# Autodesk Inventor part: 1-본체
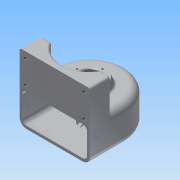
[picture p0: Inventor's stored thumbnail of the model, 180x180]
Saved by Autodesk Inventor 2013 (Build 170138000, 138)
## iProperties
Created: 2015-02
Part Number: 1-본체
Material: 알루미늄 6061
Document SubType Name: Modeling
Designer: Administrator
Density: 2.40731 g/cm^3
Mass: 511.135 g
Surface Area: 707.804 cm^2
Volume: 212.326 cm^3
Author: Administrator
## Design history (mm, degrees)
sketch "스케치1"
  geometry: L1 (-50, 0)-(-50, -50); L2 (50, 0)-(50, -50); L3 (-50, -50)-(50, -50); A1 r 50 centre (0, 0) between (-50, 0) and (50, 0); 1 further point
  constraints: 6 end point, 2 point on circle, 2 tangent, 1 centre point, 1 coincident, 1 parallel, 1 perpendicular, 1 vertical
  dimensions: "d0" = 100 diameter of A1; "d2" = 50 distance from line of L3 point (0, 0)
extrude "돌출1" new body sketch "스케치1" distance "d3" = 50; taper "d4" = 0 deg
feature "쉘1" dims "d5" = 4
sketch "스케치2"
  geometry: L1 (-50, 0)-(-50, -50) reference; L2 (-50, -50)-(50, -50) reference; L3 (50, -50)-(50, 0) reference; L4 (-50, -20)-(-34.641, -20); L5 (50, -20)-(34.641, -20); A1 r 50 centre (0, 0) between (50, 0) and (-50, 0) reference; A2 r 40 centre (0, 0) between (-34.641, -20) and (34.641, -20)
  constraints: 4 end point, 2 collinear, 2 point on circle, 2 point on line, 1 centre point, 1 coincident, 1 perpendicular
  dimensions: "d6" = 80 diameter of A2; "d9" = 30 distance between parallel lines of L2 L4
extrude "돌출2" join sketch "스케치2" distance "d10" = 45; taper "d11" = 0 deg
sketch "스케치3"
  geometry: C1 r 25 at (0, 0); A1 r 40 centre (0, 0) between (-34.641, -20) and (34.641, -20) reference
  constraints: 1 centre point, 1 coincident
  dimensions: "d12" = 50 diameter of C1
extrude "돌출3" join sketch "스케치3" distance "d14" = 10; taper "d15" = -20 deg
sketch "스케치4"
  geometry: C1 r 20 at (0, 0); A1 r 50 centre (0, 0) between (50, 0) and (-50, 0) reference
  constraints: 1 centre point, 1 coincident
  dimensions: "d16" = 40 diameter of C1
extrude "돌출4" join sketch "스케치4" distance "d18" = 9; taper "d19" = 0 deg
hole "구멍1" diameter "d22" = 20; stored, may be unused: countersink angle "d26" = 90 deg, drill point angle "d28" = 118 deg; dims "d23" = 6, "d24" = 28, "d25" = 10, "d27" = 8, "d29" = 10, "d30" = 10
hole "구멍2" diameter "d33" = 20; stored, may be unused: countersink angle "d37" = 90 deg, drill point angle "d39" = 0 deg; dims "d34" = 6, "d35" = 28, "d36" = 8, "d38" = 10, "d40" = 10, "d41" = 10
sketch "스케치5"
  geometry: L1 (0, 95)-(100, 95) reference; L2 (8.25, 86)-(91.75, 86); L3 (91.75, 86)-(91.75, 53); L4 (91.75, 53)-(8.25, 53); L5 (8.25, 53)-(8.25, 86); L6 (0, 50)-(0, 95) reference; 7 further points
  constraints: 8 end point, 4 coincident, 2 midpoint, 2 parallel, 1 horizontal, 1 perpendicular, 1 vertical alignment
  dimensions: "d42" = 83.5 distance of L2.start L2.end; "d44" = 33 distance of L4.end L2.start; "d72" = 9 distance between parallel lines of L2 L1
hole "구멍3" sketch "스케치5" at (8.25, 86), (8.25, 53), (91.75, 53), (91.75, 86) diameter "d45" = 5.134; stored, may be unused: countersink angle "d49" = 90 deg, drill point angle "d51" = 118 deg; dims "d46" = 10, "d47" = 28, "d48" = 8, "d50" = 13
sketch "스케치6"
  geometry: C1 r 14 at (0, 0) reference; C2 r 21.36 at (0, 0) reference; A1 r 18 centre (0, 0) between (0, 18) and (0, -18); 2 further points
  constraints: 4 point on circle, 2 horizontal alignment, 2 vertical alignment, 1 centre point, 1 coincident
  dimensions: "d52" = 36 diameter of A1
hole "구멍4" sketch "스케치6" at (0, 18), (0, -18), (18, 0), (-18, 0) diameter "d54" = 2.459; stored, may be unused: countersink angle "d58" = 90 deg, drill point angle "d60" = 118 deg; dims "d55" = 6, "d56" = 28, "d57" = 8, "d59" = 9
node "작업 평면1"
sketch "스케치7"
  geometry: L1 (50, 50)-(-50, 50) reference; L2 (50, 0)-(-50, 0) reference; 3 further points
  constraints: 1 midpoint, 1 vertical alignment, 1 other
  dimensions: "d61" = 25 distance from line of L2 point (0, 25)
feature "엠보싱1" sketch "스케치7" dims "d0" = 100, "d2" = 50, "d62" = 0.5, "d63" = 0
fillet "모깎기1" dims "d64" = 0.3, "d65" = 10, "d66" = 6
fillet "모깎기2" dims "d67" = 3
fillet "모깎기3" dims "d68" = 3
chamfer "모따기1" distance "d69" = 1; stored, may be unused: second distance "d70" = 2, angle "d71" = 45 deg
node "솔리드1"
